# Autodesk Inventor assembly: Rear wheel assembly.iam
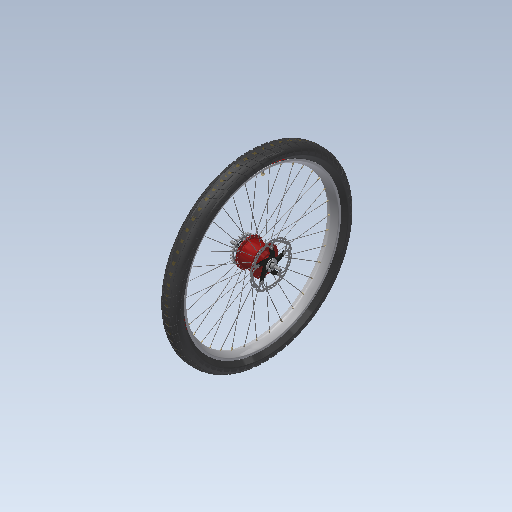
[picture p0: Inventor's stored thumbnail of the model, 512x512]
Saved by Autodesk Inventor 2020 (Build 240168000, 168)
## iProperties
Created: 2015-11
Part Number: Rear wheel assembly.iam
Material: Ogólny
Document SubType Name: Assembly
Designer: Tomasz
Sending System: SolidWorks 2017
Last Author: Tomasz
Last Saved: 2017-11-20
Author: Tomasz
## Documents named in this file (25)
- C:\Users\bruno\Documents\1-Cours-2020-21\1STI2D-2020-21\IT\6. Antivol\Inventor-Antivol\INVENTOR 2018_Steel Hardtail B+\Rear wheel assembly.iam.iam
- C:\Users\bruno\Documents\1-Cours-2020-21\1STI2D-2020-21\IT\6. Antivol\Inventor-Antivol\INVENTOR 2018_Steel Hardtail B+\Kopia Shimano Afline - SG-S7000 - 8.ipt^Rear wheel assembly.iam.ipt
- C:\Users\bruno\Documents\1-Cours-2020-21\1STI2D-2020-21\IT\6. Antivol\Inventor-Antivol\INVENTOR 2018_Steel Hardtail B+\Kopia dt Swiss xm511.ipt^Rear wheel assembly.iam.ipt
- C:\Users\bruno\Documents\1-Cours-2020-21\1STI2D-2020-21\IT\6. Antivol\Inventor-Antivol\INVENTOR 2018_Steel Hardtail B+\Kopia DT swiss 255 x 2mm - RR.ipt^Rear wheel assembly.iam.ipt
- C:\Users\bruno\Documents\1-Cours-2020-21\1STI2D-2020-21\IT\6. Antivol\Inventor-Antivol\INVENTOR 2018_Steel Hardtail B+\Kopia DT Swiss nipple.ipt^Rear wheel assembly.iam.ipt
- C:\Users\bruno\Documents\1-Cours-2020-21\1STI2D-2020-21\IT\6. Antivol\Inventor-Antivol\INVENTOR 2018_Steel Hardtail B+\Kopia DT swiss 255 x 2mm - RL.ipt^Rear wheel assembly.iam.ipt
- C:\Users\bruno\Documents\1-Cours-2020-21\1STI2D-2020-21\IT\6. Antivol\Inventor-Antivol\INVENTOR 2018_Steel Hardtail B+\Kopia Rim tubeless tape with valve.ipt^Rear wheel assembly.iam.ipt
- C:\Users\bruno\Documents\1-Cours-2020-21\1STI2D-2020-21\IT\6. Antivol\Inventor-Antivol\INVENTOR 2018_Steel Hardtail B+\Kopia valve cap.ipt^Rear wheel assembly.iam.ipt
- C:\Users\bruno\Documents\1-Cours-2020-21\1STI2D-2020-21\IT\6. Antivol\Inventor-Antivol\INVENTOR 2018_Steel Hardtail B+\Kopia Schwalbe Super Moto X 27,5 x 2,8.ipt^Rear wheel assembly.iam.ipt
- C:\Users\bruno\Documents\1-Cours-2020-21\1STI2D-2020-21\IT\6. Antivol\Inventor-Antivol\INVENTOR 2018_Steel Hardtail B+\Kopia Center Lock Nut.ipt^Rear wheel assembly.iam.ipt
- C:\Users\bruno\Documents\1-Cours-2020-21\1STI2D-2020-21\IT\6. Antivol\Inventor-Antivol\INVENTOR 2018_Steel Hardtail B+\Kopia Hub COG.ipt^Rear wheel assembly.iam.ipt
- C:\Users\bruno\Documents\1-Cours-2020-21\1STI2D-2020-21\IT\6. Antivol\Inventor-Antivol\INVENTOR 2018_Steel Hardtail B+\Kopia cog lock nut.ipt^Rear wheel assembly.iam.ipt
- C:\Users\bruno\Documents\1-Cours-2020-21\1STI2D-2020-21\IT\6. Antivol\Inventor-Antivol\INVENTOR 2018_Steel Hardtail B+\Shimano XTR 160mm.iam.iam
- Kopia Shimano Afline - SG-S7000 - 8.ipt^Rear wheel assembly.iam
- Kopia dt Swiss xm511.ipt^Rear wheel assembly.iam
- Kopia DT swiss 255 x 2mm - RR.ipt^Rear wheel assembly.iam
- Kopia DT Swiss nipple.ipt^Rear wheel assembly.iam
- Kopia DT swiss 255 x 2mm - RL.ipt^Rear wheel assembly.iam
- Kopia Rim tubeless tape with valve.ipt^Rear wheel assembly.iam
- Kopia valve cap.ipt^Rear wheel assembly.iam
- Kopia Schwalbe Super Moto X 27,5 x 2,8.ipt^Rear wheel assembly.iam
- Kopia Center Lock Nut.ipt^Rear wheel assembly.iam
- Kopia Hub COG.ipt^Rear wheel assembly.iam
- Kopia cog lock nut.ipt^Rear wheel assembly.iam
- Shimano XTR 160mm.iam
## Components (81 placed, 12 different names)
1. Kopia Shimano Afline - SG-S7000 - 8.ipt^Rear wheel assembly.iam:1
2. Kopia dt Swiss xm511.ipt^Rear wheel assembly.iam:1
3. Kopia DT swiss 255 x 2mm - RR.ipt^Rear wheel assembly.iam:1
4. Kopia DT swiss 255 x 2mm - RR.ipt^Rear wheel assembly.iam:2
5. Kopia DT swiss 255 x 2mm - RR.ipt^Rear wheel assembly.iam:3
6. Kopia DT swiss 255 x 2mm - RR.ipt^Rear wheel assembly.iam:4
7. Kopia DT swiss 255 x 2mm - RR.ipt^Rear wheel assembly.iam:5
8. Kopia DT swiss 255 x 2mm - RR.ipt^Rear wheel assembly.iam:6
9. Kopia DT swiss 255 x 2mm - RR.ipt^Rear wheel assembly.iam:7
10. Kopia DT swiss 255 x 2mm - RR.ipt^Rear wheel assembly.iam:8
11. Kopia DT swiss 255 x 2mm - RR.ipt^Rear wheel assembly.iam:9
12. Kopia DT swiss 255 x 2mm - RR.ipt^Rear wheel assembly.iam:10
13. Kopia DT swiss 255 x 2mm - RR.ipt^Rear wheel assembly.iam:11
14. Kopia DT swiss 255 x 2mm - RR.ipt^Rear wheel assembly.iam:12
15. Kopia DT swiss 255 x 2mm - RR.ipt^Rear wheel assembly.iam:13
16. Kopia DT swiss 255 x 2mm - RR.ipt^Rear wheel assembly.iam:14
17. Kopia DT swiss 255 x 2mm - RR.ipt^Rear wheel assembly.iam:15
18. Kopia DT swiss 255 x 2mm - RR.ipt^Rear wheel assembly.iam:16
19. Kopia DT swiss 255 x 2mm - RR.ipt^Rear wheel assembly.iam:17
20. Kopia DT swiss 255 x 2mm - RR.ipt^Rear wheel assembly.iam:18
21. Kopia DT Swiss nipple.ipt^Rear wheel assembly.iam:1
22. Kopia DT Swiss nipple.ipt^Rear wheel assembly.iam:2
23. Kopia DT Swiss nipple.ipt^Rear wheel assembly.iam:3
24. Kopia DT Swiss nipple.ipt^Rear wheel assembly.iam:4
25. Kopia DT Swiss nipple.ipt^Rear wheel assembly.iam:5
26. Kopia DT Swiss nipple.ipt^Rear wheel assembly.iam:6
27. Kopia DT Swiss nipple.ipt^Rear wheel assembly.iam:7
28. Kopia DT Swiss nipple.ipt^Rear wheel assembly.iam:8
29. Kopia DT Swiss nipple.ipt^Rear wheel assembly.iam:9
30. Kopia DT Swiss nipple.ipt^Rear wheel assembly.iam:10
31. Kopia DT Swiss nipple.ipt^Rear wheel assembly.iam:11
32. Kopia DT Swiss nipple.ipt^Rear wheel assembly.iam:12
33. Kopia DT Swiss nipple.ipt^Rear wheel assembly.iam:13
34. Kopia DT Swiss nipple.ipt^Rear wheel assembly.iam:14
35. Kopia DT Swiss nipple.ipt^Rear wheel assembly.iam:15
36. Kopia DT Swiss nipple.ipt^Rear wheel assembly.iam:16
37. Kopia DT Swiss nipple.ipt^Rear wheel assembly.iam:17
38. Kopia DT Swiss nipple.ipt^Rear wheel assembly.iam:18
39. Kopia DT Swiss nipple.ipt^Rear wheel assembly.iam:19
40. Kopia DT Swiss nipple.ipt^Rear wheel assembly.iam:20
41. Kopia DT Swiss nipple.ipt^Rear wheel assembly.iam:21
42. Kopia DT Swiss nipple.ipt^Rear wheel assembly.iam:22
43. Kopia DT Swiss nipple.ipt^Rear wheel assembly.iam:23
44. Kopia DT Swiss nipple.ipt^Rear wheel assembly.iam:24
45. Kopia DT Swiss nipple.ipt^Rear wheel assembly.iam:25
46. Kopia DT Swiss nipple.ipt^Rear wheel assembly.iam:26
47. Kopia DT Swiss nipple.ipt^Rear wheel assembly.iam:27
48. Kopia DT Swiss nipple.ipt^Rear wheel assembly.iam:28
49. Kopia DT Swiss nipple.ipt^Rear wheel assembly.iam:29
50. Kopia DT Swiss nipple.ipt^Rear wheel assembly.iam:30
51. Kopia DT Swiss nipple.ipt^Rear wheel assembly.iam:31
52. Kopia DT Swiss nipple.ipt^Rear wheel assembly.iam:32
53. Kopia DT Swiss nipple.ipt^Rear wheel assembly.iam:33
54. Kopia DT Swiss nipple.ipt^Rear wheel assembly.iam:34
55. Kopia DT Swiss nipple.ipt^Rear wheel assembly.iam:35
56. Kopia DT Swiss nipple.ipt^Rear wheel assembly.iam:36
57. Kopia DT swiss 255 x 2mm - RL.ipt^Rear wheel assembly.iam:1
58. Kopia DT swiss 255 x 2mm - RL.ipt^Rear wheel assembly.iam:2
59. Kopia DT swiss 255 x 2mm - RL.ipt^Rear wheel assembly.iam:3
60. Kopia DT swiss 255 x 2mm - RL.ipt^Rear wheel assembly.iam:4
61. Kopia DT swiss 255 x 2mm - RL.ipt^Rear wheel assembly.iam:5
62. Kopia DT swiss 255 x 2mm - RL.ipt^Rear wheel assembly.iam:6
63. Kopia DT swiss 255 x 2mm - RL.ipt^Rear wheel assembly.iam:7
64. Kopia DT swiss 255 x 2mm - RL.ipt^Rear wheel assembly.iam:8
65. Kopia DT swiss 255 x 2mm - RL.ipt^Rear wheel assembly.iam:9
66. Kopia DT swiss 255 x 2mm - RL.ipt^Rear wheel assembly.iam:10
67. Kopia DT swiss 255 x 2mm - RL.ipt^Rear wheel assembly.iam:11
68. Kopia DT swiss 255 x 2mm - RL.ipt^Rear wheel assembly.iam:12
69. Kopia DT swiss 255 x 2mm - RL.ipt^Rear wheel assembly.iam:13
70. Kopia DT swiss 255 x 2mm - RL.ipt^Rear wheel assembly.iam:14
71. Kopia DT swiss 255 x 2mm - RL.ipt^Rear wheel assembly.iam:15
72. Kopia DT swiss 255 x 2mm - RL.ipt^Rear wheel assembly.iam:16
73. Kopia DT swiss 255 x 2mm - RL.ipt^Rear wheel assembly.iam:17
74. Kopia DT swiss 255 x 2mm - RL.ipt^Rear wheel assembly.iam:18
75. Kopia Rim tubeless tape with valve.ipt^Rear wheel assembly.iam:1
76. Kopia valve cap.ipt^Rear wheel assembly.iam:1
77. Kopia Schwalbe Super Moto X 27,5 x 2,8.ipt^Rear wheel assembly.iam:1
78. Kopia Center Lock Nut.ipt^Rear wheel assembly.iam:1
79. Kopia Hub COG.ipt^Rear wheel assembly.iam:1
80. Kopia cog lock nut.ipt^Rear wheel assembly.iam:1
81. Shimano XTR 160mm.iam:1 [sub-assembly]
